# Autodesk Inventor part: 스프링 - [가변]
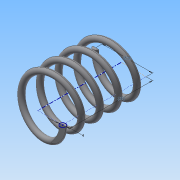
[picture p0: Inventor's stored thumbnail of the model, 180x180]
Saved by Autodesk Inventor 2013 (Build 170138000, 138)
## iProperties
Created: 2015-03
Part Number: 스프링 - [가변]
Material: 강철, 탄소
Document SubType Name: Modeling
Designer: Administrator
Density: 7.87 g/cm^3
Mass: 47.9935 g
Surface Area: 62.0176 cm^2
Volume: 6.09829 cm^3
Author: Administrator
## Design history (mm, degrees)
sketch "스케치1"
  geometry: L1 (0, 0)-(17.5, 0); L2 (17.5, 0)-(17.5, 43.5); L3 (17.5, 43.5)-(0, 43.5); L4 (0, 43.5)-(0, 0); C1 r 2 at (17.5, 0)
  constraints: 8 end point, 2 parallel, 1 centre point, 1 coincident, 1 horizontal, 1 perpendicular
  dimensions: "d0" = 4 diameter of C1; "d2" = 35 diameter of L2 L4; "d3" = 43.5 distance of L1.end L2.end (derived)
feature "코일1" sketch "스케치1" pitch "d4" = 10; turns "d6" = 4.5; dims "d5" = 43.5 (= d3), "d7" = 0, angle "d8" = 90 deg, angle "d9" = 90 deg, "d10" = 0, "d11" = 0
sketch "스케치2"
  geometry: L1 (-19.5, 0)-(-15.5, 0) reference; 1 further point
  constraints: 1 horizontal alignment
extrude "돌출1" cut sketch "스케치2" distance "d12" = 10; taper "d13" = 0 deg
node "작업 평면1"
sketch "스케치3"
  geometry: L1 (15.5, 0)-(19.5, 0) reference; 1 further point
  constraints: 1 horizontal alignment
extrude "돌출2" cut sketch "스케치3" distance "d15" = 10; taper "d16" = 0 deg
node "솔리드1"
node "절단 모서리 투영1"
node "절단 모서리 투영2"
other parameters: "d14" = 43.5 (= d3)
